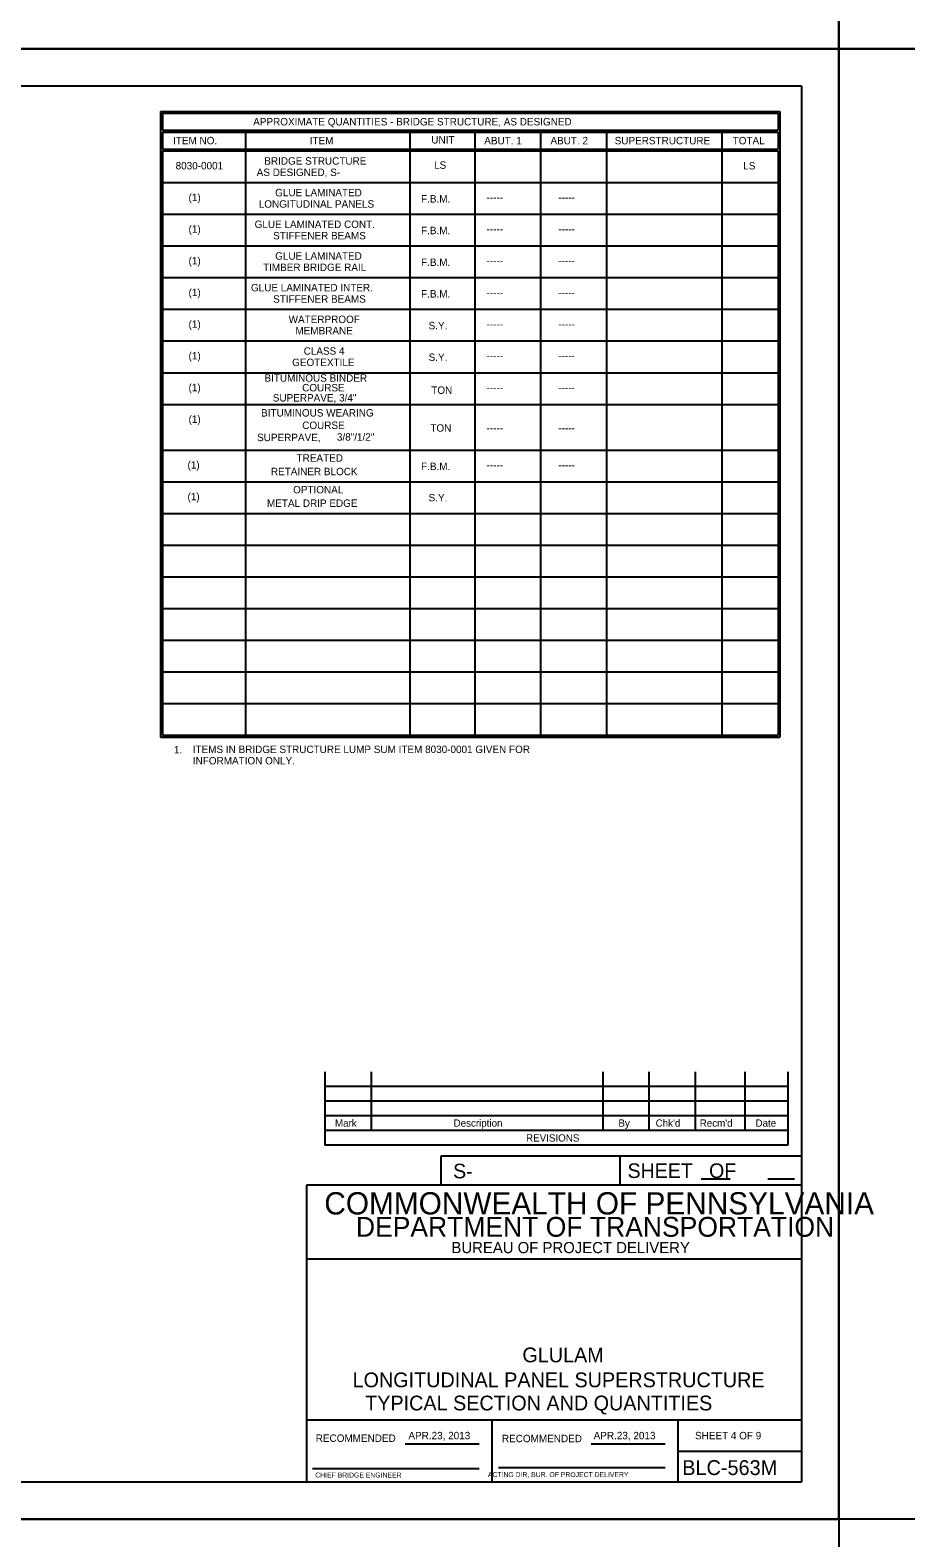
# Model space of a CAD drawing. Extents: x 638268 to 640277, y 295465 to 298435.
# Drawn here: x 638950 to 639304, y 296052 to 296661 of the extents above; entities that cross this region are included whole.
import ezdxf

# ---------------------------------------------------------------- set-up
doc = ezdxf.new("R2010")
doc.units = 0
for name, color, linetype in [('1', 7, 'Continuous'), ('2', 7, 'Continuous'), ('4', 7, 'Continuous'), ('PLT-BNDY', 7, 'Continuous')]:
    doc.layers.add(name, color=color, linetype=linetype)

msp = doc.modelspace()

# ---------------------------------------------------------------- linework, layer by layer
at = {"layer": '2'}
for p, q in [((638475.46, 296638.46), (639261.46, 296638.46)), ((639261.46, 296638.46), (639261.46, 296074.46)), ((639068.92, 296240.15), (639068.92, 296210.62)), ((639087.62, 296240.15), (639087.62, 296216.53)), ((639181.13, 296240.15), (639181.13, 296216.53)), ((639199.83, 296240.15), (639199.83, 296216.53)), ((639218.53, 296240.15), (639218.53, 296216.53)), ((639238.59, 296240.15), (639238.59, 296216.53)), ((639255.94, 296240.15), (639255.94, 296210.62)), ((639255.94, 296234.24), (639068.92, 296234.24)), ((639255.94, 296228.34), (639068.92, 296228.34)), ((639255.94, 296222.43), (639068.92, 296222.43)), ((639255.94, 296216.53), (639068.92, 296216.53)), ((639255.94, 296210.62), (639068.92, 296210.62)), ((639261.46, 296206.11), (639115.78, 296206.11)), ((639115.78, 296206.11), (639115.78, 296194.46)), ((639188.09, 296206.11), (639188.09, 296194.46)), ((639261.46, 296206.11), (639261.46, 296194.46)), ((639261.46, 296194.46), (639061.46, 296194.46)), ((639061.46, 296194.46), (639061.46, 296074.46)), ((639261.46, 296194.46), (639115.78, 296194.46)), ((639220.95, 296197), (639232.6, 296197)), ((639247.83, 296197), (639258.56, 296197)), ((639261.46, 296164.46), (639061.46, 296164.46)), ((639261.46, 296099.46), (639061.46, 296099.46)), ((639136.46, 296074.46), (639136.46, 296099.46)), ((639211.46, 296099.46), (639211.46, 296074.46)), ((639101.42, 296089.96), (639131.19, 296089.96)), ((639176.42, 296089.96), (639206.33, 296089.96)), ((639211.46, 296086.96), (639261.46, 296086.96)), ((639063.96, 296079.96), (639131.19, 296079.96)), ((639139.08, 296080.33), (639206.33, 296080.33)), ((639261.46, 296074.46), (638475.46, 296074.46))]:
    msp.add_line(p, q, dxfattribs=at)
at = {"layer": '4'}
for p, q in [((639002.61, 296628.16), (639002.61, 296375.43)), ((639002.61, 296628.16), (639252.74, 296628.16)), ((639003.35, 296627.43), (639252, 296627.43)), ((639003.35, 296627.43), (639003.35, 296620.54)), ((639252, 296627.43), (639252, 296620.54)), ((639252.74, 296628.16), (639252.74, 296375.43)), ((639003.35, 296620.54), (639252, 296620.54)), ((639003.35, 296619.8), (639252, 296619.8)), ((639003.35, 296619.8), (639003.35, 296612.91)), ((639036.91, 296619.8), (639036.91, 296612.91)), ((639103.22, 296619.8), (639103.22, 296612.91)), ((639129.53, 296619.8), (639129.53, 296612.91)), ((639156.08, 296619.8), (639156.08, 296612.91)), ((639182.63, 296619.8), (639182.63, 296612.91)), ((639229.27, 296619.8), (639229.27, 296612.91)), ((639252, 296619.8), (639252, 296612.91)), ((639003.35, 296612.91), (639036.91, 296612.91)), ((639003.35, 296612.17), (639252, 296612.17)), ((639003.35, 296612.17), (639003.35, 296376.17)), ((639036.91, 296612.91), (639104.79, 296612.91)), ((639036.91, 296612.17), (639036.91, 296376.17)), ((639103.22, 296612.17), (639103.22, 296376.17)), ((639104.79, 296612.91), (639129.53, 296612.91)), ((639129.53, 296612.91), (639157.95, 296612.91)), ((639129.53, 296612.17), (639129.53, 296376.17)), ((639156.08, 296612.17), (639156.08, 296376.17)), ((639157.95, 296612.91), (639182.63, 296612.91)), ((639182.63, 296612.91), (639229.27, 296612.91)), ((639182.63, 296612.17), (639182.63, 296376.17)), ((639229.27, 296612.91), (639252, 296612.91)), ((639229.27, 296612.17), (639229.27, 296376.17)), ((639252, 296612.17), (639252, 296376.17)), ((639003.35, 296599.38), (639252, 296599.38)), ((639003.35, 296586.58), (639252, 296586.58)), ((639003.35, 296573.79), (639252, 296573.79)), ((639003.35, 296560.99), (639252, 296560.99)), ((639003.35, 296548.2), (639252, 296548.2)), ((639003.35, 296535.4), (639252, 296535.4)), ((639003.35, 296522.6), (639252, 296522.6)), ((639003.35, 296509.81), (639252, 296509.81)), ((639003.35, 296491.33), (639252, 296491.33)), ((639003.35, 296478.53), (639252, 296478.53)), ((639003.35, 296465.74), (639252, 296465.74)), ((639003.35, 296452.94), (639252, 296452.94)), ((639003.35, 296440.15), (639252, 296440.15)), ((639003.35, 296427.35), (639252, 296427.35)), ((639003.35, 296414.55), (639252, 296414.55)), ((639003.35, 296401.76), (639252, 296401.76)), ((639003.35, 296401.76), (639252, 296401.76)), ((639003.35, 296388.97), (639252, 296388.97)), ((639003.35, 296376.17), (639252, 296376.17)), ((639003.35, 296376.17), (639252, 296376.17)), ((639002.61, 296375.43), (639252.74, 296375.43))]:
    msp.add_line(p, q, dxfattribs=at)
at = {"layer": 'PLT-BNDY'}
for points in [[(638435.46, 297247.46), (639276.46, 297247.46), (639276.46, 296653.46), (638435.46, 296653.46)], [(639276.46, 297247.46), (640117.46, 297247.46), (640117.46, 296653.46), (639276.46, 296653.46)], [(638435.46, 296653.46), (639276.46, 296653.46), (639276.46, 296059.46), (638435.46, 296059.46)], [(639276.46, 296653.46), (640117.46, 296653.46), (640117.46, 296059.46), (639276.46, 296059.46)], [(638435.46, 296059.46), (639276.46, 296059.46), (639276.46, 295465.46), (638435.46, 295465.46)]]:
    msp.add_lwpolyline(points, close=True, dxfattribs=at)

# ---------------------------------------------------------------- texts
at = {"layer": '1'}
msp.add_text('SHEET 4 OF 9', height=3, dxfattribs=at).set_placement((639218.43, 296091.76))
at = {"layer": '2'}
for s, height, p in [('Mark', 2.952, (639073.02, 296218.03)), ('Description', 2.9523, (639120.92, 296218.03)), ('By', 2.952, (639187.49, 296218.03)), ("Chk'd", 2.952, (639202.52, 296218.03)), ("Recm'd", 2.953, (639220.33, 296218.03)), ('Date', 2.952, (639242.86, 296218.03)), ('REVISIONS', 2.952, (639150.2, 296212.01)), ('S-', 5.905, (639120.73, 296197.17)), ('COMMONWEALTH OF PENNSYLVANIA', 9, (639068.71, 296182.58)), ('DEPARTMENT OF TRANSPORTATION', 8.0002, (639081.46, 296173.58)), ('BUREAU OF PROJECT DELIVERY', 4.5, (639120.05, 296166.96)), ('TYPICAL SECTION AND QUANTITIES', 5.9714, (639085.2, 296103.43)), ('APR.23, 2013', 3, (639102.67, 296091.77)), ('APR.23, 2013', 3, (639177.48, 296091.77)), ('CHIEF BRIDGE ENGINEER', 2.0002, (639065.05, 296076.33)), ('  ACTING DIR, BUR. OF PROJECT DELIVERY', 2.0002, (639133.23, 296076.51)), ('BLC-563M', 6, (639213.27, 296077.33))]:
    msp.add_text(s, height=height, dxfattribs=at).set_placement(p)
for s, height, p in [('SHEET   OF', 5.907, (639191.18, 296197.31)), ('RECOMMENDED', 3, (639065.23, 296090.71)), ('RECOMMENDED', 3, (639140.44, 296090.58))]:
    msp.add_text(s, height=height, rotation=360, dxfattribs=at).set_placement(p)
at = {"layer": '4'}
for s, height, p in [('APPROXIMATE QUANTITIES - BRIDGE STRUCTURE, AS DESIGNED', 3, (639039.99, 296622.47)), ('ITEM NO.', 3, (639007.6, 296614.85)), ('ITEM', 3, (639062.82, 296614.85)), ('UNIT', 3, (639111.93, 296615.16)), ('ABUT. 1', 3, (639133.3, 296614.84)), ('ABUT. 2', 3, (639160.05, 296614.84)), ('SUPERSTRUCTURE', 3, (639185.99, 296614.84)), ('TOTAL', 3, (639233.63, 296614.85)), ('8030-0001', 3, (639008.66, 296604.7)), ('BRIDGE STRUCTURE', 3, (639044.46, 296606.63)), ('LS', 3, (639113.04, 296604.95)), ('LS', 3, (639237.89, 296604.7)), ('AS DESIGNED, S-     ', 3, (639041.41, 296602.04)), ('GLUE LAMINATED', 3, (639048.86, 296593.84)), ('(1)', 3, (639013.88, 296591.9)), ('LONGITUDINAL PANELS', 3, (639042.23, 296589.25)), ('F.B.M.', 3, (639107.79, 296591.31)), ('-----', 3, (639134.25, 296591.9)), ('-----', 3, (639163.24, 296591.9)), ('GLUE LAMINATED CONT.', 3, (639040.56, 296581.04)), ('(1)', 3, (639013.88, 296579.11)), ('STIFFENER BEAMS', 3, (639048.02, 296576.45)), ('F.B.M.', 3, (639107.79, 296578.52)), ('-----', 3, (639134.25, 296579.11)), ('-----', 3, (639163.24, 296579.11)), ('GLUE LAMINATED', 3, (639048.86, 296568.25)), ('(1)', 3, (639013.88, 296566.31)), ('TIMBER BRIDGE RAIL', 3, (639043.95, 296563.66)), ('F.B.M.', 3, (639107.79, 296565.72)), ('-----', 3, (639134.25, 296566.31)), ('-----', 3, (639163.24, 296566.31)), ('(1)', 3, (639013.88, 296553.52)), ('GLUE LAMINATED INTER.', 3, (639039.07, 296555.45)), ('STIFFENER BEAMS', 3, (639048.02, 296550.86)), ('F.B.M.', 3, (639107.79, 296552.93)), ('-----', 3, (639134.25, 296553.51)), ('-----', 3, (639163.24, 296553.51)), ('(1)', 3, (639013.88, 296540.72)), ('WATERPROOF', 3, (639054.3, 296542.66)), ('MEMBRANE', 3, (639057.03, 296538.07)), ('S.Y.', 3, (639110.83, 296540.13)), ('-----', 3, (639134.25, 296540.72)), ('-----', 3, (639163.24, 296540.72)), ('(1)', 3, (639013.88, 296527.93)), ('GEOTEXTILE', 3, (639055.71, 296525.27)), ('CLASS 4', 3, (639060.36, 296529.86)), ('S.Y.', 3, (639110.83, 296527.34)), ('-----', 3, (639134.25, 296527.93)), ('-----', 3, (639163.24, 296527.93)), ('(1)', 3, (639013.88, 296515.13)), ('BITUMINOUS BINDER', 3, (639044.53, 296518.96)), ('COURSE', 3, (639059.75, 296515.04)), ('TON', 3, (639111.9, 296514.04)), ('-----', 3, (639134.25, 296515.13)), ('-----', 3, (639163.24, 296515.13)), ('SUPERPAVE, 3/4"', 3, (639047.9, 296510.95)), ('(1)', 3, (639013.88, 296502.34)), ('BITUMINOUS WEARING', 3, (639043.17, 296504.88)), ('SUPERPAVE,', 3, (639041.56, 296494.95)), ('COURSE', 3, (639059.77, 296499.85)), ('3/8"/1/2"', 3, (639073.79, 296495.14)), ('TON', 3, (639111.54, 296498.76)), ('-----', 3, (639134.25, 296498.78)), ('-----', 3, (639163.24, 296498.78)), ('TREATED', 3, (639057.51, 296486.64)), ('F.B.M.', 3, (639107.79, 296483.26)), ('RETAINER BLOCK', 3, (639047.13, 296481.19)), ('-----', 3, (639134.25, 296483.85)), ('-----', 3, (639163.24, 296483.85)), ('OPTIONAL', 3, (639056.1, 296473.85)), ('S.Y.', 3, (639110.83, 296470.62)), ('METAL DRIP EDGE', 3, (639045.56, 296468.4)), ('1.', 3, (639007.95, 296368.78)), ('ITEMS IN BRIDGE STRUCTURE LUMP SUM ITEM 8030-0001 GIVEN FOR', 3, (639015.57, 296368.96)), ('INFORMATION ONLY.', 3, (639015.6, 296364.37)), ('GLULAM', 5.971, (639148.71, 296122.86)), ('LONGITUDINAL PANEL SUPERSTRUCTURE', 5.9714, (639080.13, 296112.78))]:
    msp.add_text(s, height=height, dxfattribs=at).set_placement(p)
for p in [(639013.45, 296483.85), (639013.45, 296471.05)]:
    msp.add_text('(1)', height=3, rotation=360, dxfattribs=at).set_placement(p)

doc.saveas('drawing.dxf')
